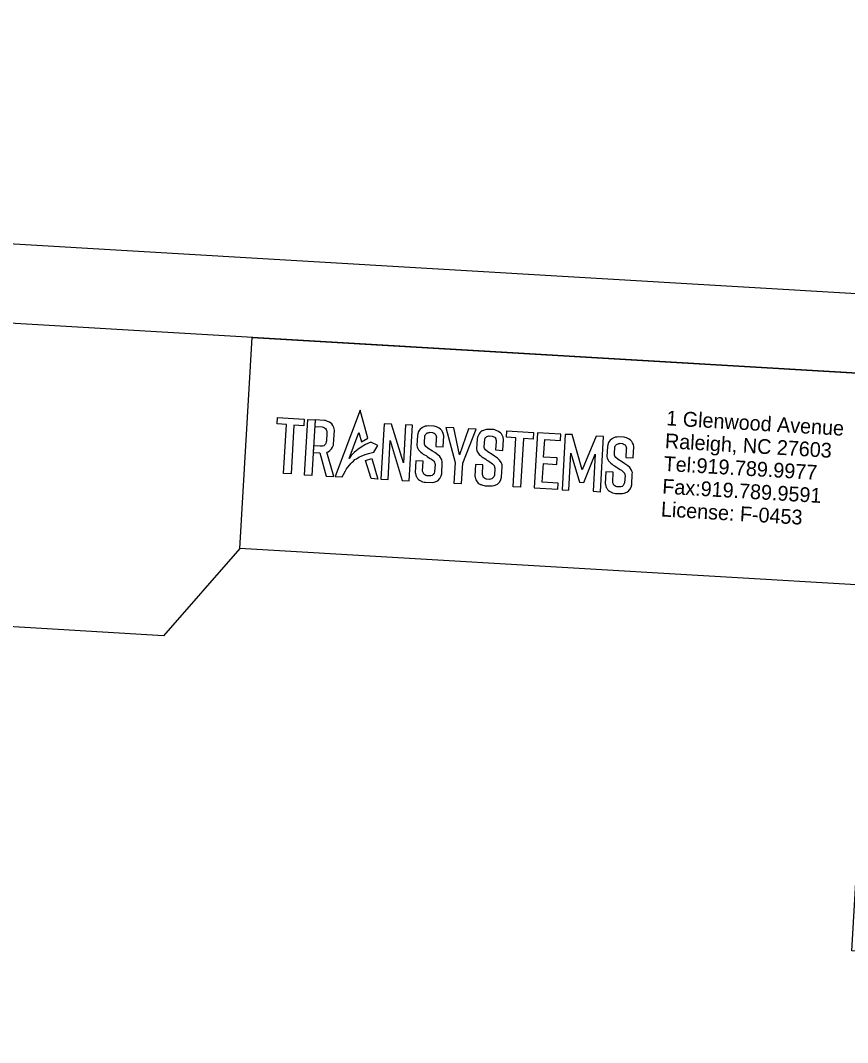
# Model space of a CAD drawing. Extents: x 2010737 to 2012732, y 444258 to 445456.
# Drawn here: x 2012233.4 to 2012494.2, y 445134 to 445456.4 of the extents above; entities that cross this region are included whole.
import ezdxf

# ---------------------------------------------------------------- set-up
doc = ezdxf.new("R2010")
doc.units = 0
for name, color, linetype in [('Old_Level_1', 7, 'Continuous'), ('Old_Level_2', 7, 'Continuous'), ('Old_Level_58', 7, 'Continuous'), ('Sheet Clip Boundary CELL', 7, 'Continuous'), ('Sheet Plan And Profile CELL', 7, 'Continuous'), ('Sheet Plot Border Outside CELL', 7, 'Continuous')]:
    doc.layers.add(name, color=color, linetype=linetype)

msp = doc.modelspace()

# ---------------------------------------------------------------- linework, layer by layer
at = {"layer": 'Old_Level_1'}
for points in [[(2012340.56, 445333.43), (2012332.66, 445312.53), (2012334.87, 445312.41), (2012335.26, 445313.23), (2012335.91, 445314.35), (2012336.25, 445314.96), (2012336.66, 445315.48), (2012337.23, 445316.2), (2012337.58, 445316.65), (2012337.98, 445317.02), (2012338.39, 445317.39), (2012338.9, 445317.86), (2012339.33, 445318.1), (2012339.76, 445318.41), (2012340.34, 445318.7), (2012340.84, 445318.95), (2012342.09, 445319.45), (2012343.11, 445319.8), (2012344.79, 445320.26), (2012346.05, 445322.33), (2012343.93, 445323.41), (2012342.25, 445322.62), (2012340.82, 445321.8), (2012339.8, 445321.06), (2012339.25, 445320.67), (2012338.68, 445320.13), (2012338.12, 445319.6), (2012337.69, 445319.2), (2012337.28, 445318.57), (2012337.05, 445318.23), (2012340.16, 445326.44), (2012340.99, 445323.49), (2012342.96, 445324.63)], [(2012314.42, 445331.12), (2012322.87, 445330.63), (2012322.75, 445328.56), (2012319.65, 445328.74), (2012318.75, 445313.34), (2012316.41, 445313.48), (2012317.31, 445328.98), (2012314.34, 445329.15)], [(2012324.02, 445330.55), (2012326.33, 445330.42), (2012325.32, 445312.88), (2012323.01, 445313.01)], [(2012326.21, 445328.33), (2012328.6, 445328.2), (2012328.9, 445328.13), (2012329.29, 445327.94), (2012329.6, 445327.71), (2012329.81, 445327.42), (2012329.95, 445327.08), (2012330.05, 445326.82), (2012330.02, 445326.24), (2012329.89, 445323.75), (2012329.8, 445323.43), (2012329.69, 445322.98), (2012329.55, 445322.7), (2012329.33, 445322.45), (2012329.05, 445322.25), (2012328.62, 445322.13), (2012328.29, 445322.11), (2012327.96, 445322.08), (2012325.86, 445322.19), (2012325.74, 445320.09), (2012327.85, 445319.98), (2012329.79, 445312.69), (2012332.21, 445312.57), (2012330, 445320.25), (2012330.39, 445320.37), (2012330.95, 445320.73), (2012331.47, 445321.24), (2012331.85, 445321.85), (2012332.1, 445322.47), (2012332.1, 445322.66), (2012332.41, 445327.21), (2012332.25, 445327.97), (2012331.93, 445328.66), (2012331.55, 445329.16), (2012330.88, 445329.67), (2012330.21, 445329.94), (2012329.55, 445330.2), (2012329.15, 445330.23), (2012326.33, 445330.42)], [(2012348.09, 445329.17), (2012347.08, 445311.74), (2012349.32, 445311.61), (2012350.03, 445323.87), (2012353.75, 445311.32), (2012356, 445311.22), (2012357, 445328.69), (2012354.83, 445328.82), (2012354.14, 445316.86), (2012350.45, 445329.04)], [(2012364.4, 445322.02), (2012366.71, 445321.89), (2012366.91, 445325.36), (2012366.75, 445326.08), (2012366.51, 445326.68), (2012366.23, 445327.09), (2012365.88, 445327.46), (2012365.46, 445327.77), (2012365.05, 445327.97), (2012365.05, 445327.97), (2012364.6, 445328.19), (2012364.13, 445328.34), (2012363.81, 445328.44), (2012362.06, 445328.5), (2012361.53, 445328.45), (2012361.07, 445328.39), (2012360.6, 445328.18), (2012360.18, 445327.99), (2012359.77, 445327.73), (2012359.44, 445327.44), (2012359.18, 445327.09), (2012358.96, 445326.71), (2012358.66, 445326.03), (2012358.58, 445325.51), (2012358.4, 445322.35), (2012358.48, 445321.87), (2012358.68, 445321.36), (2012358.95, 445320.94), (2012359.23, 445320.61), (2012359.66, 445320.23), (2012360.09, 445319.86), (2012360.36, 445319.63), (2012360.83, 445319.37), (2012361.3, 445319.12), (2012361.67, 445318.84), (2012362.09, 445318.53), (2012362.61, 445318.23), (2012363.02, 445317.99), (2012363.44, 445317.65), (2012363.73, 445317.34), (2012363.96, 445317.08), (2012364.09, 445316.6), (2012364.16, 445316.29), (2012364, 445314.06), (2012363.81, 445313.59), (2012363.54, 445313.18), (2012363.19, 445312.91), (2012362.83, 445312.77), (2012362.49, 445312.72), (2012361.52, 445312.76), (2012361.21, 445312.87), (2012360.89, 445313.08), (2012360.57, 445313.29), (2012360.45, 445313.63), (2012360.33, 445313.98), (2012360.23, 445314.25), (2012360.38, 445317.36), (2012358.04, 445317.47), (2012357.87, 445313.76), (2012357.97, 445313.47), (2012358.19, 445312.6), (2012358.35, 445312.3), (2012358.58, 445311.96), (2012358.94, 445311.57), (2012359.23, 445311.36), (2012359.65, 445311.15), (2012359.81, 445311.07), (2012360.23, 445310.87), (2012360.76, 445310.78), (2012361.15, 445310.72), (2012363.29, 445310.65), (2012363.89, 445310.75), (2012364.74, 445311.08), (2012365.02, 445311.19), (2012365.69, 445311.94), (2012366.07, 445312.71), (2012366.27, 445313.41), (2012366.41, 445316.83), (2012366.43, 445317.3), (2012366.33, 445317.68), (2012366.15, 445318.05), (2012365.66, 445318.83), (2012364.99, 445319.43), (2012364.05, 445320.07), (2012363.33, 445320.56), (2012361.92, 445321.41), (2012361.2, 445322.01), (2012360.89, 445322.45), (2012360.83, 445322.74), (2012360.77, 445323.03), (2012360.96, 445325.45), (2012361.1, 445325.7), (2012361.24, 445325.95), (2012361.42, 445326.09), (2012361.67, 445326.27), (2012361.93, 445326.36), (2012362.2, 445326.45), (2012362.34, 445326.42), (2012362.36, 445326.49), (2012363.32, 445326.42), (2012363.59, 445326.29), (2012363.86, 445326.17), (2012364.13, 445326.04), (2012364.25, 445325.84), (2012364.41, 445325.55), (2012364.49, 445325.27), (2012364.57, 445324.99), (2012364.54, 445324.69)], [(2012370.03, 445327.88), (2012367.49, 445328.03), (2012370.47, 445316.96), (2012370.11, 445310.42), (2012372.5, 445310.29), (2012372.85, 445316.77), (2012377.15, 445327.51), (2012374.65, 445327.58), (2012371.86, 445319.39)], [(2012383.24, 445320.93), (2012385.55, 445320.8), (2012385.75, 445324.27), (2012385.6, 445324.98), (2012385.35, 445325.59), (2012385.07, 445326), (2012384.73, 445326.37), (2012384.3, 445326.68), (2012383.89, 445326.88), (2012383.89, 445326.88), (2012383.44, 445327.1), (2012382.97, 445327.25), (2012382.65, 445327.35), (2012380.9, 445327.41), (2012380.37, 445327.35), (2012379.91, 445327.3), (2012379.44, 445327.09), (2012379.02, 445326.9), (2012378.61, 445326.64), (2012378.28, 445326.35), (2012378.02, 445326), (2012377.8, 445325.61), (2012377.51, 445324.93), (2012377.42, 445324.42), (2012377.24, 445321.26), (2012377.33, 445320.78), (2012377.52, 445320.27), (2012377.79, 445319.84), (2012378.07, 445319.52), (2012378.5, 445319.14), (2012378.93, 445318.77), (2012379.2, 445318.53), (2012379.67, 445318.28), (2012380.14, 445318.03), (2012380.51, 445317.75), (2012380.93, 445317.44), (2012381.45, 445317.14), (2012381.86, 445316.9), (2012382.28, 445316.56), (2012382.57, 445316.24), (2012382.8, 445315.99), (2012382.93, 445315.5), (2012383, 445315.2), (2012382.84, 445312.97), (2012382.65, 445312.49), (2012382.38, 445312.09), (2012382.03, 445311.82), (2012381.67, 445311.68), (2012381.33, 445311.63), (2012380.37, 445311.66), (2012380.05, 445311.77), (2012379.73, 445311.99), (2012379.41, 445312.2), (2012379.29, 445312.54), (2012379.17, 445312.88), (2012379.07, 445313.16), (2012379.22, 445316.27), (2012376.88, 445316.38), (2012376.71, 445312.67), (2012376.81, 445312.38), (2012377.03, 445311.51), (2012377.19, 445311.2), (2012377.42, 445310.87), (2012377.78, 445310.47), (2012378.07, 445310.26), (2012378.49, 445310.06), (2012378.65, 445309.98), (2012379.07, 445309.77), (2012379.6, 445309.69), (2012379.99, 445309.63), (2012382.13, 445309.56), (2012382.73, 445309.66), (2012383.58, 445309.99), (2012383.86, 445310.1), (2012384.53, 445310.85), (2012384.91, 445311.61), (2012385.11, 445312.31), (2012385.25, 445315.73), (2012385.27, 445316.21), (2012385.17, 445316.59), (2012384.99, 445316.95), (2012384.5, 445317.74), (2012383.83, 445318.34), (2012382.89, 445318.98), (2012382.17, 445319.46), (2012380.76, 445320.31), (2012380.04, 445320.92), (2012379.73, 445321.36), (2012379.67, 445321.65), (2012379.61, 445321.93), (2012379.8, 445324.36), (2012379.94, 445324.61), (2012380.08, 445324.85), (2012380.27, 445324.99), (2012380.51, 445325.18), (2012380.77, 445325.27), (2012381.04, 445325.36), (2012381.18, 445325.32), (2012381.2, 445325.4), (2012382.16, 445325.32), (2012382.43, 445325.2), (2012382.7, 445325.07), (2012382.97, 445324.95), (2012383.09, 445324.75), (2012383.26, 445324.46), (2012383.33, 445324.18), (2012383.41, 445323.9), (2012383.38, 445323.59)], [(2012386.76, 445326.92), (2012395.21, 445326.43), (2012395.09, 445324.36), (2012391.98, 445324.54), (2012391.09, 445309.15), (2012388.75, 445309.28), (2012389.64, 445324.78), (2012386.68, 445324.95)], [(2012403.8, 445325.93), (2012396.43, 445326.35), (2012395.42, 445308.96), (2012402.88, 445308.52), (2012402.99, 445310.49), (2012397.95, 445310.78), (2012398.29, 445316.62), (2012402.5, 445316.37), (2012402.62, 445318.44), (2012398.38, 445318.69), (2012398.7, 445324.18), (2012403.7, 445323.89)], [(2012410.52, 445314.66), (2012407.36, 445325.79), (2012405.15, 445325.81), (2012404.21, 445308.38), (2012406.31, 445308.26), (2012406.94, 445319.92), (2012409.67, 445310.76), (2012411.02, 445310.65), (2012414.62, 445319.58), (2012413.97, 445307.88), (2012416.25, 445307.75), (2012417.21, 445325.15), (2012414.91, 445325.27)], [(2012424.3, 445318.55), (2012426.61, 445318.42), (2012426.81, 445321.89), (2012426.66, 445322.6), (2012426.41, 445323.21), (2012426.14, 445323.61), (2012425.79, 445323.99), (2012425.37, 445324.3), (2012424.95, 445324.49), (2012424.95, 445324.49), (2012424.51, 445324.71), (2012424.03, 445324.86), (2012423.72, 445324.96), (2012421.97, 445325.03), (2012421.43, 445324.97), (2012420.97, 445324.92), (2012420.5, 445324.71), (2012420.08, 445324.52), (2012419.67, 445324.26), (2012419.34, 445323.96), (2012419.08, 445323.61), (2012418.86, 445323.23), (2012418.57, 445322.55), (2012418.49, 445322.04), (2012418.3, 445318.88), (2012418.39, 445318.39), (2012418.59, 445317.89), (2012418.85, 445317.46), (2012419.13, 445317.13), (2012419.56, 445316.76), (2012419.99, 445316.39), (2012420.26, 445316.15), (2012420.73, 445315.9), (2012421.2, 445315.64), (2012421.57, 445315.37), (2012422, 445315.06), (2012422.51, 445314.76), (2012422.93, 445314.51), (2012423.34, 445314.17), (2012423.63, 445313.86), (2012423.87, 445313.61), (2012423.99, 445313.12), (2012424.07, 445312.82), (2012423.9, 445310.59), (2012423.71, 445310.11), (2012423.44, 445309.71), (2012423.1, 445309.44), (2012422.73, 445309.3), (2012422.39, 445309.25), (2012421.43, 445309.28), (2012421.11, 445309.39), (2012420.79, 445309.6), (2012420.48, 445309.82), (2012420.36, 445310.16), (2012420.23, 445310.5), (2012420.14, 445310.77), (2012420.28, 445313.88), (2012417.95, 445313.99), (2012417.77, 445310.29), (2012417.87, 445310), (2012418.09, 445309.12), (2012418.25, 445308.82), (2012418.48, 445308.49), (2012418.84, 445308.09), (2012419.13, 445307.88), (2012419.56, 445307.67), (2012419.71, 445307.6), (2012420.13, 445307.39), (2012420.66, 445307.31), (2012421.05, 445307.24), (2012423.19, 445307.17), (2012423.79, 445307.28), (2012424.64, 445307.6), (2012424.93, 445307.71), (2012425.59, 445308.47), (2012425.97, 445309.23), (2012426.17, 445309.93), (2012426.32, 445313.35), (2012426.34, 445313.82), (2012426.23, 445314.21), (2012426.06, 445314.57), (2012425.57, 445315.36), (2012424.89, 445315.96), (2012423.95, 445316.59), (2012423.23, 445317.08), (2012421.82, 445317.93), (2012421.1, 445318.54), (2012420.8, 445318.98), (2012420.74, 445319.26), (2012420.67, 445319.55), (2012420.86, 445321.98), (2012421, 445322.22), (2012421.14, 445322.47), (2012421.33, 445322.61), (2012421.57, 445322.79), (2012421.84, 445322.89), (2012422.1, 445322.98), (2012422.25, 445322.94), (2012422.26, 445323.01), (2012423.22, 445322.94), (2012423.49, 445322.82), (2012423.76, 445322.69), (2012424.03, 445322.57), (2012424.15, 445322.36), (2012424.32, 445322.08), (2012424.39, 445321.79), (2012424.47, 445321.51), (2012424.44, 445321.21)], [(2012342.25, 445317.6), (2012344.21, 445318.25), (2012346.09, 445311.69), (2012344, 445311.89)]]:
    msp.add_lwpolyline(points, close=True, dxfattribs=at)
at = {"layer": 'Old_Level_58'}
msp.add_lwpolyline([(2012306.5, 445356.39), (2012506.21, 445344.62), (2012502.28, 445278.05), (2012302.58, 445289.82)], close=True, dxfattribs=at)
at = {"layer": 'Sheet Clip Boundary CELL'}
msp.add_lwpolyline([(2011147.85, 444375), (2012145.7, 444317.47), (2012151.4, 444414.1), (2011981.99, 444424.08), (2012065.05, 444531.98), (2012116.09, 444528.98), (2012447, 444433.71), (2012447.13, 444434.15), (2012512.37, 444430.3), (2012650.6, 444422.19), (2012665.49, 444675.78), (2012620.99, 444678.39), (2012629.52, 444823.68), (2012643.65, 445063.27), (2012648.58, 445153.9), (2012495.5, 445162.92), (2012502.28, 445278.05), (2012302.58, 445289.82), (2012278.52, 445262.33), (2012176.97, 445268.45), (2011765.99, 445293.2), (2011771.61, 445387.92), (2011477.93, 445405.24)], dxfattribs=at)
at = {"layer": 'Sheet Plan And Profile CELL'}
msp.add_lwpolyline([(2012705.91, 445332.85), (2011208.51, 445421.12), (2011146.72, 444372.94), (2012644.12, 444284.67)], close=True, dxfattribs=at)
at = {"layer": 'Sheet Plot Border Outside CELL'}
msp.add_lwpolyline([(2010970.55, 444358.28), (2012667.61, 444258.24), (2012732.34, 445356.33), (2011035.28, 445456.37)], close=True, dxfattribs=at)

# ---------------------------------------------------------------- texts
at = {"layer": 'Old_Level_2'}
for s, p in [('1 Glenwood Avenue', (2012436.95, 445328.7)), ('Raleigh, NC 27603', (2012436.53, 445321.52)), ('Tel:919.789.9977 ', (2012436.1, 445314.34)), ('Fax:919.789.9591', (2012435.68, 445307.15)), ('License: F-0453', (2012435.26, 445299.97))]:
    msp.add_text(s, height=4.6576, rotation=356.6264, dxfattribs=at).set_placement(p)

doc.saveas('drawing.dxf')
